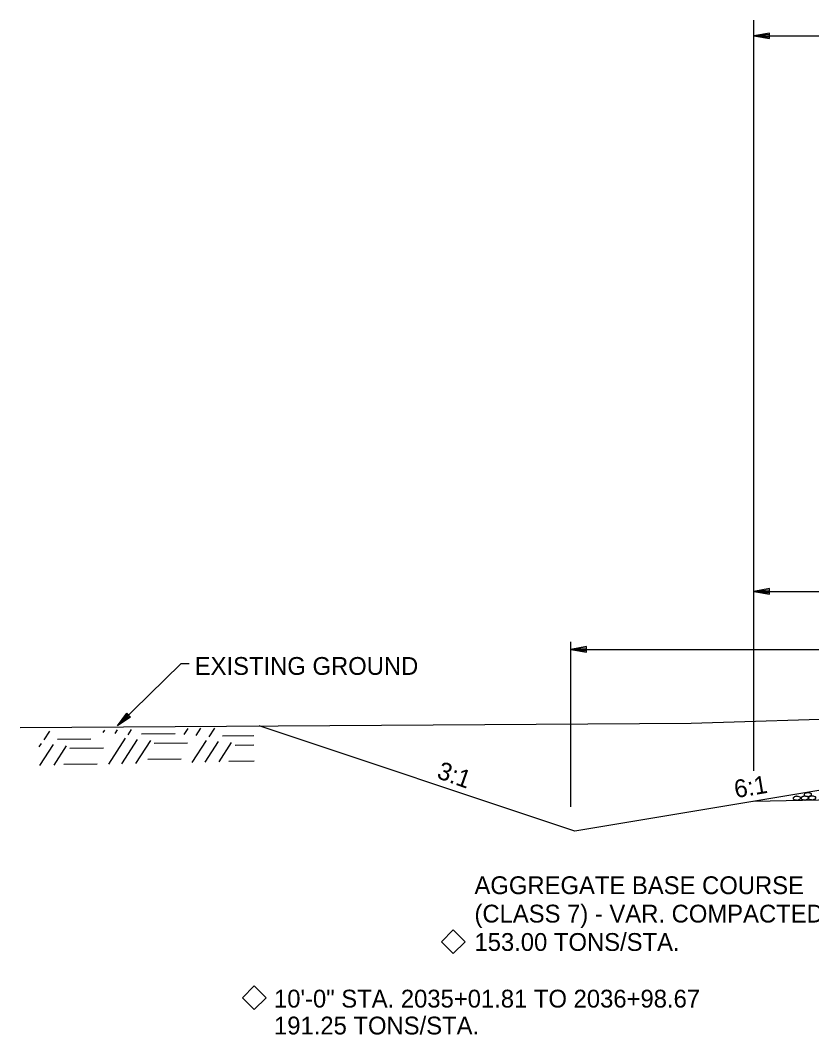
# Model space of a CAD drawing. Extents: x 1734743 to 1735935, y 759845 to 763831.
# Drawn here: x 1735609.8 to 1735663.2, y 763489.4 to 763557.7 of the extents above; entities that cross this region are included whole.
import ezdxf

# ---------------------------------------------------------------- set-up
doc = ezdxf.new("R2010")
doc.units = 0
for name, color, linetype in [('1', 7, 'Continuous'), ('10', 7, 'Continuous'), ('19', 7, 'Continuous'), ('Level 1', 7, 'Continuous')]:
    doc.layers.add(name, color=color, linetype=linetype)

# ---------------------------------------------------------------- blocks, each defined once
blk = doc.blocks.new('ROCKS')
at = {"layer": '1'}
blk.add_spline([(0.013, 0.06), (0.053, 0.053), (0.107, 0.033), (0.133, 0.013), (0.133, -0.007), (0.12, -0.033), (0.107, -0.04), (0.073, -0.053), (0.033, -0.067), (0.013, -0.067), (-0.02, -0.06), (-0.06, -0.053), (-0.087, -0.047), (-0.113, -0.02), (-0.113, -0.007), (-0.107, 0.02), (-0.087, 0.033), (-0.067, 0.047), (-0.033, 0.053), (-0.02, 0.06), (0.013, 0.06)], degree=3, dxfattribs=at)

msp = doc.modelspace()

# ---------------------------------------------------------------- linework, layer by layer
at = {"layer": '10'}
for points in [[(1735639.005, 763496.424), (1735639.8, 763495.628), (1735639.005, 763494.833), (1735638.209, 763495.628)], [(1735625.596, 763492.657), (1735626.391, 763491.861), (1735625.596, 763491.066), (1735624.8, 763491.861)]]:
    msp.add_lwpolyline(points, close=True, dxfattribs=at)
at = {"layer": '19'}
for p, q in [((1735659.253, 763520.275), (1735659.253, 763557.69)), ((1735660.304, 763556.827), (1735659.253, 763556.644)), ((1735659.253, 763556.644), (1735730.618, 763556.644)), ((1735659.253, 763556.644), (1735660.303, 763556.46)), ((1735660.304, 763556.731), (1735659.533, 763556.67)), ((1735659.533, 763556.617), (1735660.303, 763556.547)), ((1735660.303, 763556.46), (1735660.304, 763556.827)), ((1735659.253, 763507.144), (1735659.253, 763520.275)), ((1735660.304, 763519.409), (1735659.253, 763519.225)), ((1735659.253, 763519.225), (1735670.932, 763519.225)), ((1735659.253, 763519.225), (1735660.303, 763519.041)), ((1735660.304, 763519.313), (1735659.533, 763519.251)), ((1735659.533, 763519.199), (1735660.303, 763519.129)), ((1735660.303, 763519.041), (1735660.304, 763519.409)), ((1735646.932, 763504.704), (1735646.932, 763515.822)), ((1735647.982, 763515.505), (1735646.932, 763515.322)), ((1735647.982, 763515.409), (1735647.212, 763515.348)), ((1735647.982, 763515.138), (1735647.982, 763515.505)), ((1735646.932, 763515.322), (1735676.932, 763515.322)), ((1735646.932, 763515.322), (1735647.982, 763515.138)), ((1735647.212, 763515.296), (1735647.982, 763515.225)), ((1735616.387, 763510.159), (1735617.009, 763511.025)), ((1735617.262, 763510.763), (1735616.387, 763510.159)), ((1735616.571, 763510.369), (1735617.07, 763510.955)), ((1735617.201, 763510.824), (1735616.606, 763510.334)), ((1735617.009, 763511.025), (1735617.262, 763510.763)), ((1735615.415, 763509.726), (1735615.516, 763509.882)), ((1735616.214, 763509.648), (1735616.376, 763509.898)), ((1735617.106, 763509.573), (1735617.328, 763509.916)), ((1735620.87, 763509.589), (1735621.129, 763509.988)), ((1735621.669, 763509.511), (1735621.988, 763510.005)), ((1735622.56, 763509.435), (1735622.941, 763510.023)), ((1735647.204, 763503.072), (1735625.915, 763510.168)), ((1735611.438, 763509.224), (1735611.819, 763509.812)), ((1735612.327, 763509.278), (1735614.589, 763509.302)), ((1735615.801, 763507.593), (1735616.925, 763509.328)), ((1735616.661, 763507.609), (1735617.724, 763509.25)), ((1735617.995, 763509.627), (1735620.257, 763509.651)), ((1735621.414, 763507.699), (1735622.379, 763509.19)), ((1735623.449, 763509.489), (1735625.555, 763509.512)), ((1735611.107, 763508.746), (1735611.257, 763508.979)), ((1735611.152, 763507.504), (1735612.056, 763508.902)), ((1735612.104, 763507.522), (1735612.948, 763508.826)), ((1735613.173, 763508.663), (1735615.435, 763508.688)), ((1735617.613, 763507.627), (1735618.615, 763509.175)), ((1735618.841, 763509.012), (1735621.103, 763509.036)), ((1735622.274, 763507.715), (1735623.178, 763509.113)), ((1735623.226, 763507.734), (1735624.07, 763509.037)), ((1735624.295, 763508.874), (1735625.567, 763508.888)), ((1735618.417, 763507.928), (1735620.678, 763507.952)), ((1735612.749, 763507.579), (1735615.011, 763507.604)), ((1735623.871, 763507.79), (1735625.587, 763507.809)), ((1735670.932, 763507.026), (1735647.204, 763503.072)), ((1735712.954, 763506.154), (1735659.253, 763505.08))]:
    msp.add_line(p, q, dxfattribs=at)
for points in [[(1735621.212, 763514.335), (1735620.643, 763514.335), (1735616.387, 763510.159)], [(1735609.825, 763510.063), (1735655.044, 763510.358), (1735666.593, 763510.698), (1735670.546, 763510.196), (1735676.027, 763510.256), (1735685.968, 763510.652), (1735692.6, 763510.611), (1735701.593, 763510.733), (1735708.711, 763511.038)]]:
    msp.add_lwpolyline(points, dxfattribs=at)

# ---------------------------------------------------------------- block references
at = {"layer": 'Level 1', "xscale": 2.011654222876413, "yscale": 2.011654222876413, "rotation": 1.8263814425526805}
for p in [(1735662.145, 763505.302), (1735662.667, 763505.308), (1735662.878, 763505.547), (1735663.166, 763505.322)]:
    msp.add_blockref('ROCKS', p, dxfattribs=at)

# ---------------------------------------------------------------- texts
at = {"layer": '19'}
msp.add_text('EXISTING GROUND', height=1.2, dxfattribs=at).set_placement((1735621.58, 763513.602))
for s, rotation, p in [('3:1', 340.49426, (1735637.831, 763506.673)), ('6:1', 9.45113, (1735658.039, 763505.3)), ('AGGREGATE BASE COURSE', 360, (1735640.432, 763498.834)), ('(CLASS 7) - VAR. COMPACTED DEPTH', 360, (1735640.432, 763496.922)), ('153.00 TONS/STA.', 360, (1735640.432, 763495.011)), ('10\'-0" STA. 2035+01.81 TO 2036+98.67', 359.99538, (1735626.924, 763491.197)), ('191.25 TONS/STA.', 359.99538, (1735626.924, 763489.384))]:
    msp.add_text(s, height=1.2, rotation=rotation, dxfattribs=at).set_placement(p)

doc.saveas('drawing.dxf')
